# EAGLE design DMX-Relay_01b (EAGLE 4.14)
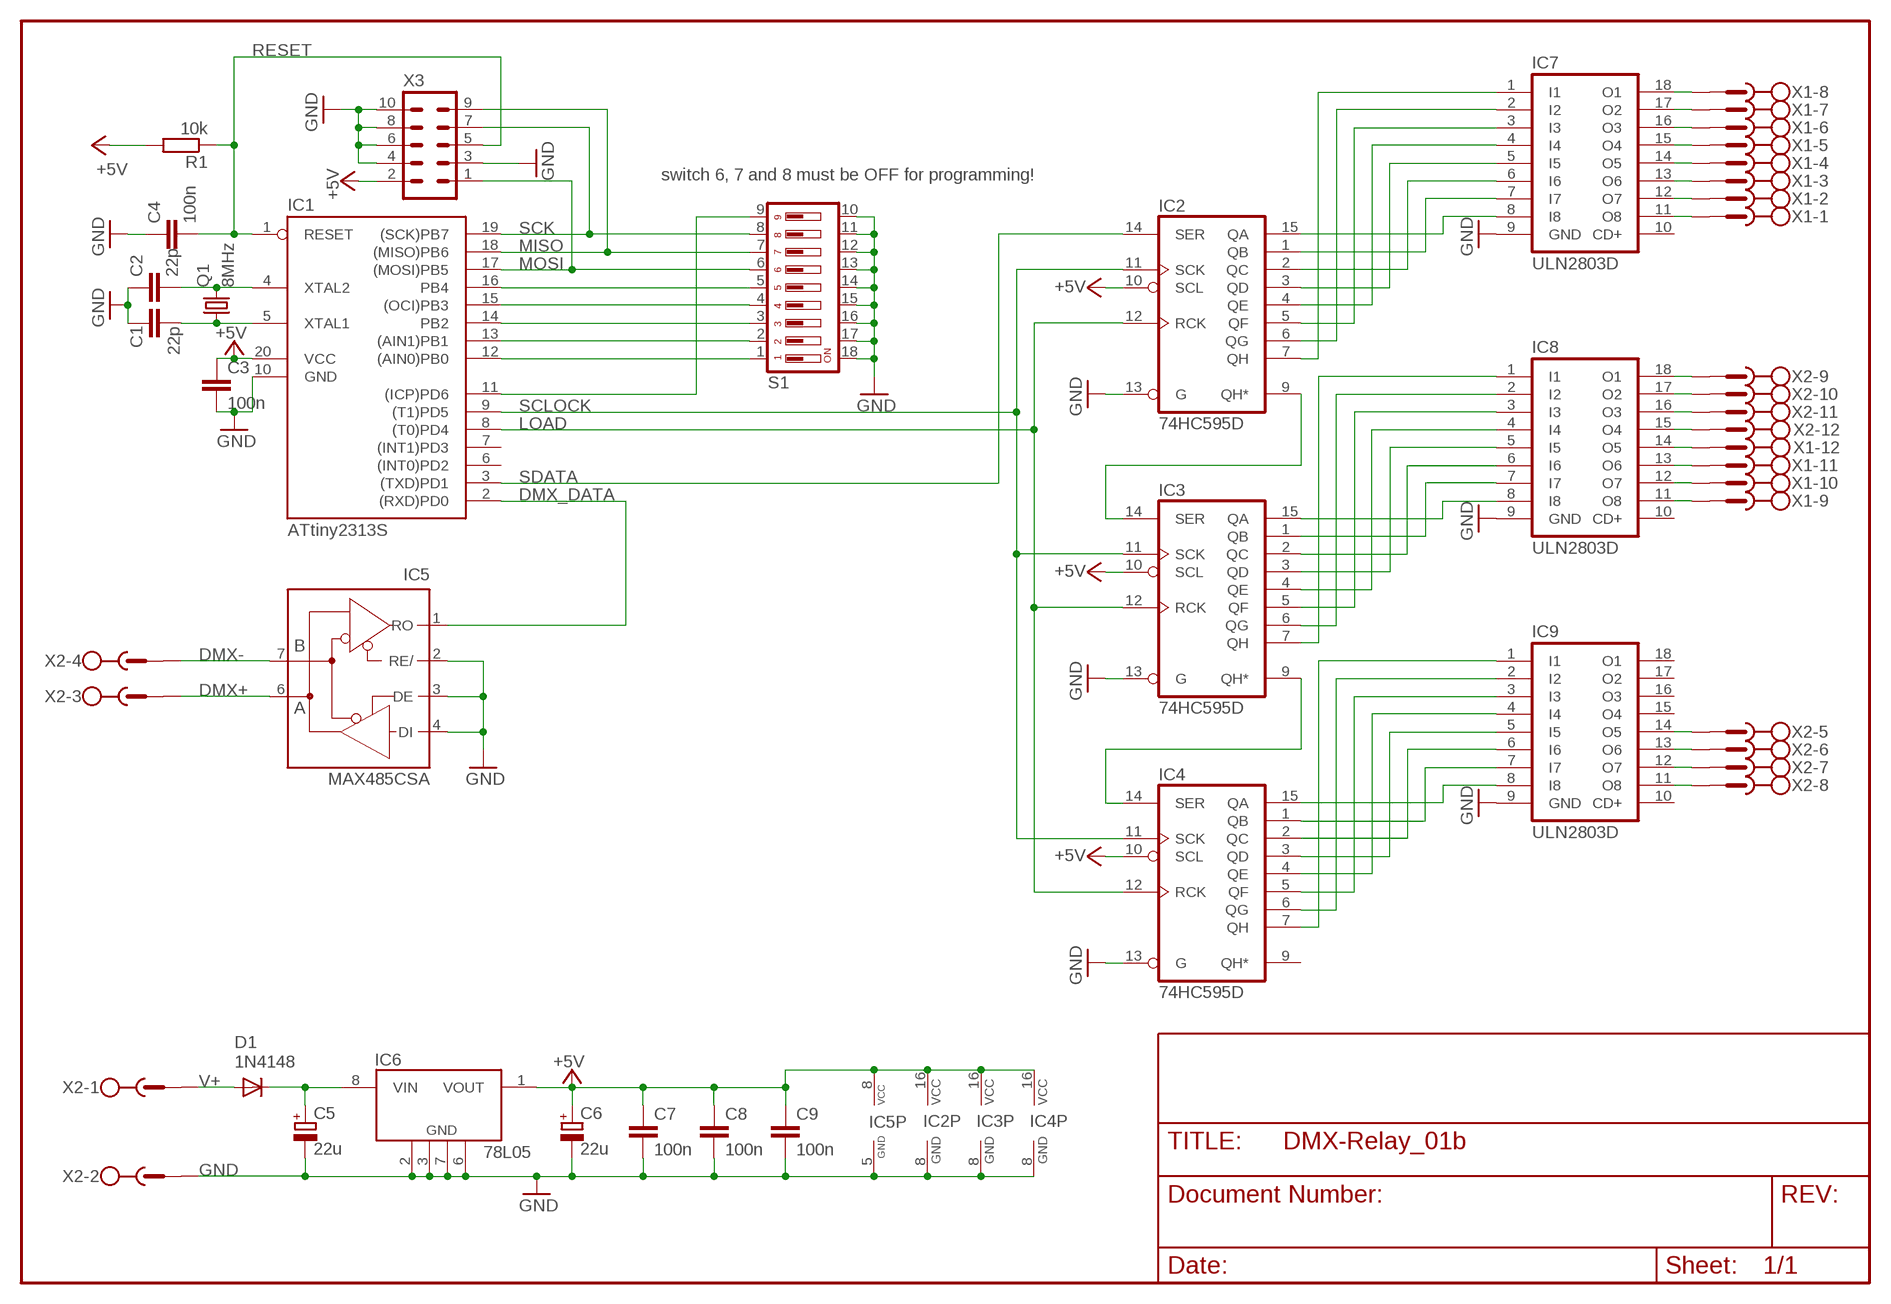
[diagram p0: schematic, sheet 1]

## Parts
C1  22p  C-EUC0805K  [C0805K]
C2  22p  C-EUC0805K  [C0805K]
C3  100n  C-EUC0805K  [C0805K]
C4  100n  C-EUC0805K  [C0805K]
C5  22u  CPOL-EUE2-5  [E2-5]
C6  22u  CPOL-EUE2-5  [E2-5]
C7  100n  C-EUC0805K  [C0805K]
C8  100n  C-EUC0805K  [C0805K]
C9  100n  C-EUC0805K  [C0805K]
D1  1N4148  DIODE-MINIMELF  [MINIMELF]
IC1  ATtiny2313S  AT90S2313S  [SO20W]
IC2  74HC595D  [SO16]
IC3  74HC595D  [SO16]
IC4  74HC595D  [SO16]
IC5  MAX485CSA  MAX481CSA  [SO08]
IC6  78L05  78LXX  [SO8]
IC7  ULN2803D  ULN2803ASOP  [SOP18]
IC8  ULN2803D  ULN2803ASOP  [SOP18]
IC9  ULN2803D  ULN2803ASOP  [SOP18]
Q1  8MHz  CRYTALHC49S  [HC49/S]
R1  10k  R-EU_M0805  [M0805]
S1  DIP09YL  [DIP09YL]
X1  MSTBV12  [MSTBV12]
X2  MSTBV12  [MSTBV12]
X3  ML10  [ML10]

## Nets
+5V: C3.1 C6.+ C7.1 C8.1 C9.1 IC1.20(VCC) IC2.10(SCL) IC2.16(VCC) IC3.10(SCL) IC3.16(VCC) IC4.10(SCL) IC4.16(VCC) IC5.8(VCC) IC6.1(VOUT) R1.2 X3.2
DMX+: IC5.6(A) X2.3
DMX-: IC5.7(B) X2.4
DMX_DATA: IC1.2((RXD)PD0) IC5.1(RO)
GND: C1.1 C2.1 C3.2 C4.1 C5.- C6.- C7.2 C8.2 C9.2 IC1.10(GND) IC2.8(GND) IC2.13(G) IC3.8(GND) IC3.13(G) IC4.8(GND) IC4.13(G) IC5.2(RE/) IC5.3(DE) IC5.4(DI) IC5.5(GND) IC6.2(GND1) IC6.3(GND2) IC6.6(GND4) IC6.7(GND3) IC7.9(GND) IC8.9(GND) IC9.9(GND) S1.10 S1.11 S1.12 S1.13 S1.14 S1.15 S1.16 S1.17 S1.18 X2.2 X3.3 X3.4 X3.6 X3.8 X3.10
LOAD: IC1.8((T0)PD4) IC2.12(RCK) IC3.12(RCK) IC4.12(RCK)
MISO: IC1.18((MISO)PB6) S1.7 X3.9
MOSI: IC1.17((MOSI)PB5) S1.6 X3.1
N$1: IC7.11(O8) X1.1
N$2: C2.2 IC1.4(XTAL2) Q1.2
N$3: C1.2 IC1.5(XTAL1) Q1.1
N$4: IC3.9(QH*) IC4.14(SER)
N$5: IC2.9(QH*) IC3.14(SER)
N$6: C5.+ D1.C IC6.8(VIN)
N$7: IC1.12((AIN0)PB0) S1.1
N$8: IC1.13((AIN1)PB1) S1.2
N$9: IC1.14(PB2) S1.3
N$10: IC7.13(O6) X1.3
N$11: IC7.15(O4) X1.5
N$12: IC1.15((OCI)PB3) S1.4
N$13: IC7.17(O2) X1.7
N$14: IC7.12(O7) X1.2
N$15: IC7.14(O5) X1.4
N$16: IC7.16(O3) X1.6
N$17: IC7.18(O1) X1.8
N$18: IC8.11(O8) X1.9
N$19: IC8.13(O6) X1.11
N$20: IC8.17(O2) X2.10
N$21: IC8.15(O4) X2.12
N$22: IC8.12(O7) X1.10
N$23: IC8.14(O5) X1.12
N$24: IC8.18(O1) X2.9
N$25: IC8.16(O3) X2.11
N$26: IC9.13(O6) X2.6
N$27: IC9.12(O7) X2.7
N$28: IC1.16(PB4) S1.5
N$29: IC3.3(QD) IC8.5(I5)
N$30: IC3.2(QC) IC8.6(I6)
N$31: IC2.7(QH) IC7.1(I1)
N$32: IC2.6(QG) IC7.2(I2)
N$33: IC2.5(QF) IC7.3(I3)
N$34: IC2.4(QE) IC7.4(I4)
N$35: IC2.3(QD) IC7.5(I5)
N$36: IC2.2(QC) IC7.6(I6)
N$37: IC2.1(QB) IC7.7(I7)
N$38: IC2.15(QA) IC7.8(I8)
N$39: IC3.7(QH) IC8.1(I1)
N$40: IC3.6(QG) IC8.2(I2)
N$41: IC3.5(QF) IC8.3(I3)
N$42: IC3.4(QE) IC8.4(I4)
N$43: IC3.1(QB) IC8.7(I7)
N$44: IC3.15(QA) IC8.8(I8)
N$45: IC4.7(QH) IC9.1(I1)
N$46: IC4.6(QG) IC9.2(I2)
N$47: IC4.5(QF) IC9.3(I3)
N$48: IC4.4(QE) IC9.4(I4)
N$49: IC4.3(QD) IC9.5(I5)
N$50: IC4.2(QC) IC9.6(I6)
N$51: IC4.1(QB) IC9.7(I7)
N$52: IC4.15(QA) IC9.8(I8)
N$53: IC9.11(O8) X2.8
N$54: IC9.14(O5) X2.5
N$55: IC1.11((ICP)PD6) S1.9
RESET: C4.2 IC1.1(RESET) R1.1 X3.5
SCK: IC1.19((SCK)PB7) S1.8 X3.7
SCLOCK: IC1.9((T1)PD5) IC2.11(SCK) IC3.11(SCK) IC4.11(SCK)
SDATA: IC1.3((TXD)PD1) IC2.14(SER)
V+: D1.A X2.1
Unconnected: IC1.6((INT0)PD2) IC1.7((INT1)PD3) IC4.9(QH*) IC7.10(CD+) IC8.10(CD+) IC9.10(CD+) IC9.15(O4) IC9.16(O3) IC9.17(O2) IC9.18(O1)

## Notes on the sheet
- switch 6, 7 and 8 must be OFF for programming!

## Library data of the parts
C1-C4 C7-C9 = rcl:C-EU: CAPACITOR, European symbol
C5 C6 = rcl:CPOL-EU: POLARIZED CAPACITOR, European symbol
D1 = diode:DIODE-: DIODE
IC1 = atmel:AT90S2313: MICROCONTROLLER 2 Kbytes FLASH 128 bytes SRAM 128 bytes EEPROM UART
IC2-IC4 = 74xx-eu:74*595: 8-bit SHIFT REGISTER, output latch
IC5 = maxim:MAX481CSA: RS485 TRANSEIVER
IC6 = selfmade:78LXX
IC7-IC9 = selfmade:ULN2803A: DRIVER ARRAY
Q1 = crystal:CRYTAL: CRYSTAL
R1 = rcl:R-EU_: RESISTOR, European symbol
S1 = switch-dil:DIP09YL: DIL/CODE SWITCH
X1 X2 = con-phoenix-500:MSTBV12: PHOENIX
X3 = con-harting-ml:ML10: HARTING

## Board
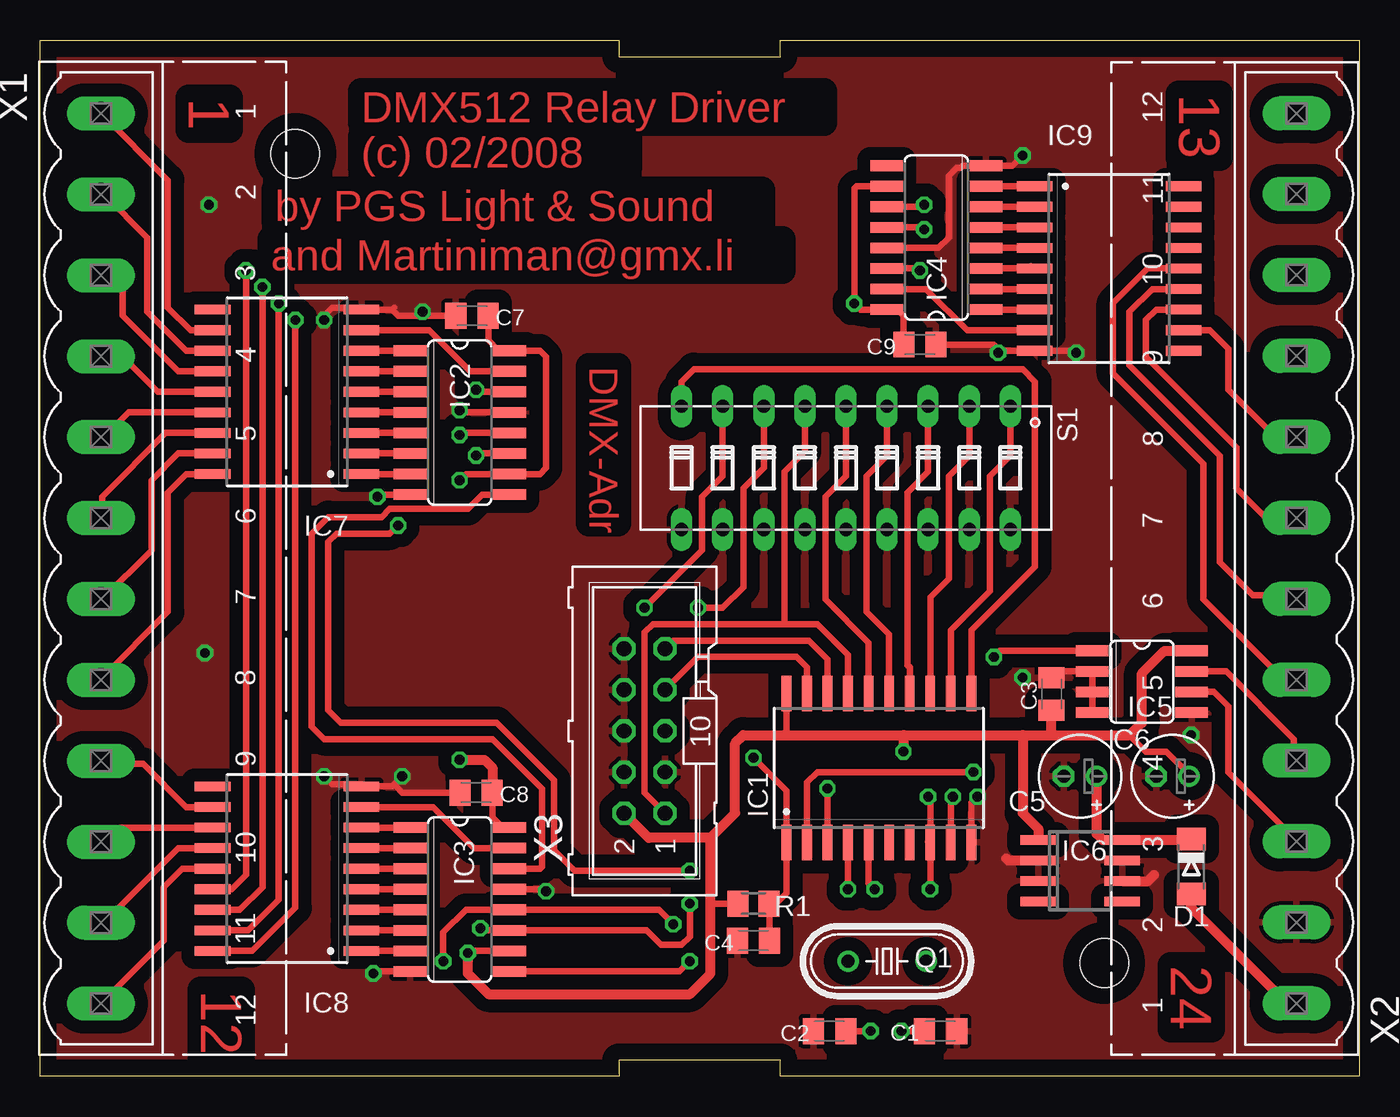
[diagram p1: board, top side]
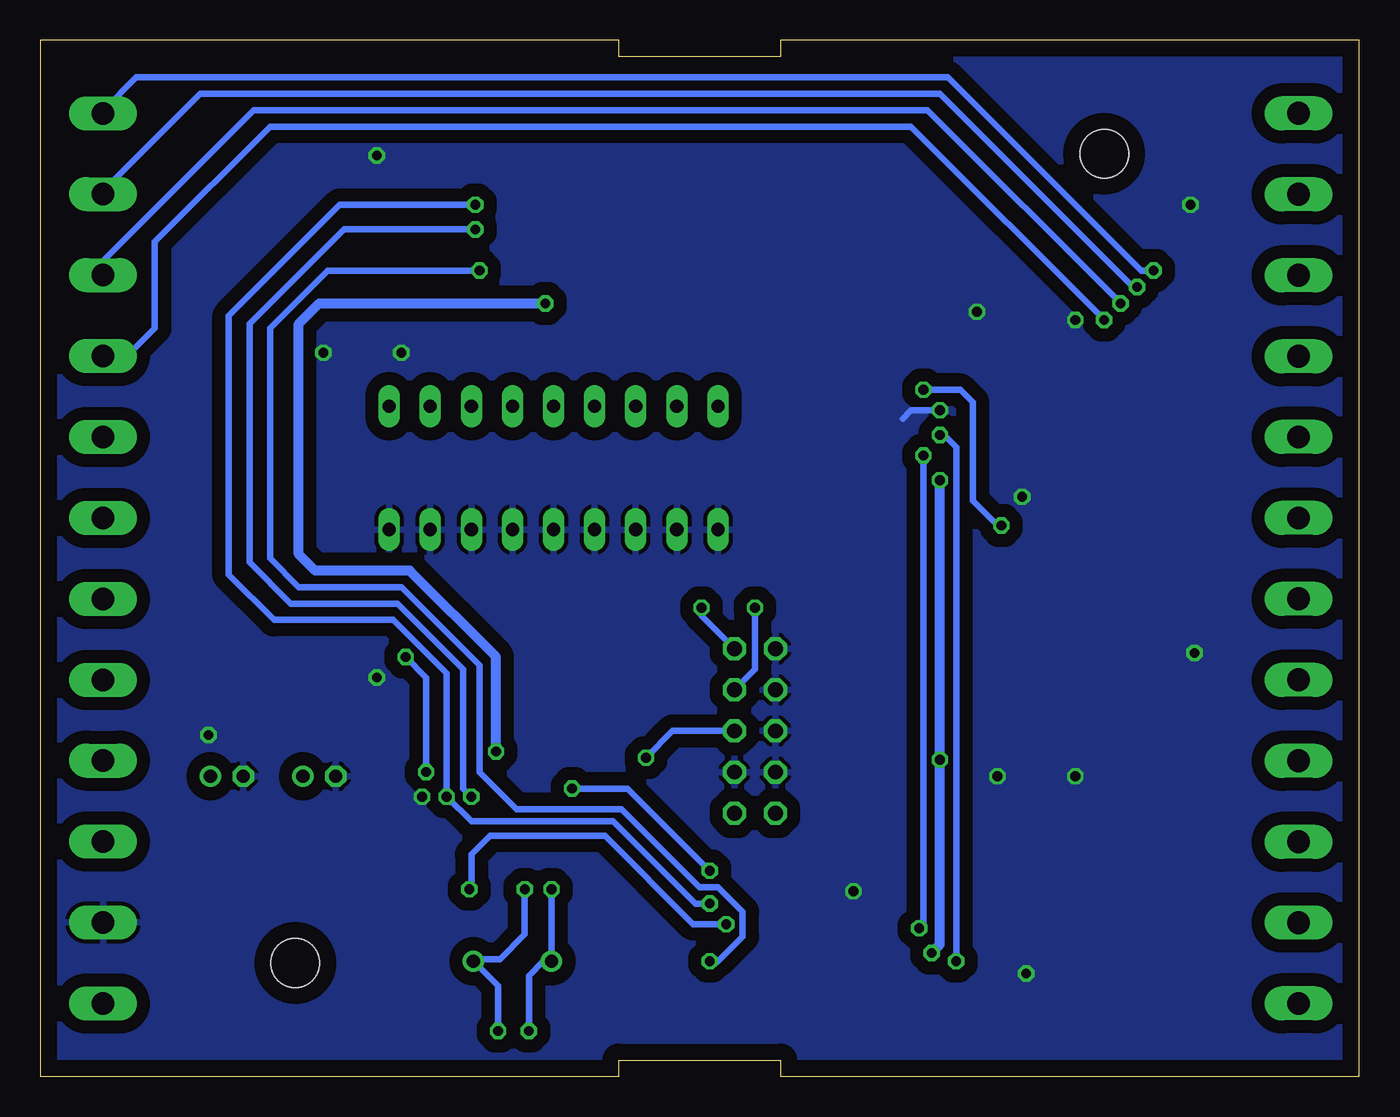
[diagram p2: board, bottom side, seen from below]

Size 81.5 x 64 mm. Coordinates in mm from the lower left corner, seen from the top.
Outline: 0,64 35.75,64 35.75,63 45.75,63 45.75,64 81.5,64 81.5,0 45.75,0 45.75,1 35.75,1 35.75,0 0,0 0,64
Copper layers (1*16): Top 0.035mm / dielectric 1.5mm / Bottom 0.035mm
Design rules "default": minimum track width 10mil, minimum drill 0.6mm, track to track 12mil, track to pad 12mil, pad to pad 12mil, via to via 12mil, smd to smd 8mil, copper to edge 40mil, drill to drill 8mil, minimum pad ring 10mil, minimum via ring 8mil, stop-mask expansion 4mil, vias tented up to drill 0mil, thermal gap 10mil
Holes 3 mm at 15.75,57 65.75,7

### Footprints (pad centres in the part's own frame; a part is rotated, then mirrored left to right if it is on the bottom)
C0805K = smd 1.3 x 1.6: 1 -1,0; 2 1,0
E2-5 = drill 0.813 pad 1.27 round: + -1.016,0 | drill 0.813 pad 1.27 octagon: - 1.016,0
MINIMELF = smd 1.4 x 1.8: A 1.7,0; C -1.7,0
SO20W = smd 0.6 x 2.2: 1 -5.715,-4.6; 2 -4.445,-4.6; 3 -3.175,-4.6; 4 -1.905,-4.6; 5 -0.635,-4.6; 6 0.635,-4.6; 7 1.905,-4.6; 8 3.175,-4.6; 9 4.445,-4.6; 10 5.715,-4.6; 11 5.715,4.6; 12 4.445,4.6; 13 3.175,4.6; 14 1.905,4.6; 15 0.635,4.6; 16 -0.635,4.6; 17 -1.905,4.6; 18 -3.175,4.6; 19 -4.445,4.6; 20 -5.715,4.6
SO16 = smd 0.66 x 2.032: 1 -4.445,-3.073; 2 -3.175,-3.073; 3 -1.905,-3.073; 4 -0.635,-3.073; 5 0.635,-3.073; 6 1.905,-3.073; 7 3.175,-3.073; 8 4.445,-3.073; 9 4.445,3.073; 10 3.175,3.073; 11 1.905,3.073; 12 0.635,3.073; 13 -0.635,3.073; 14 -1.905,3.073; 15 -3.175,3.073; 16 -4.445,3.073
SO08 = smd 0.66 x 2.032: 1 -1.905,-3.073; 2 -0.635,-3.073; 3 0.635,-3.073; 4 1.905,-3.073; 5 1.905,3.073; 6 0.635,3.073; 7 -0.635,3.073; 8 -1.905,3.073
SO8 = smd 0.6 x 2.2: 1 -1.905,-2.6; 2 -0.635,-2.6; 3 0.635,-2.6; 4 1.905,-2.6; 5 1.905,2.6; 6 0.635,2.6; 7 -0.635,2.6; 8 -1.905,2.6
SOP18 = smd 0.6 x 2.2: 1 -5.08,-4.6; 2 -3.81,-4.6; 3 -2.54,-4.6; 4 -1.27,-4.6; 5 0,-4.6; 6 1.27,-4.6; 7 2.54,-4.6; 8 3.81,-4.6; 9 5.08,-4.6; 10 5.08,4.6; 11 3.81,4.6; 12 2.54,4.6; 13 1.27,4.6; 14 0,4.6; 15 -1.27,4.6; 16 -2.54,4.6; 17 -3.81,4.6; 18 -5.08,4.6
HC49/S = drill 0.813 round: 1 -2.413,0; 2 2.413,0
M0805 = smd 1.3 x 1.6: 1 -0.95,0; 2 0.95,0
DIP09YL = drill 0.813 long: 1 -10.16,-3.81; 2 -7.62,-3.81; 3 -5.08,-3.81; 4 -2.54,-3.81; 5 0,-3.81; 6 2.54,-3.81; 7 5.08,-3.81; 8 7.62,-3.81; 9 10.16,-3.81; 10 10.16,3.81; 11 7.62,3.81; 12 5.08,3.81; 13 2.54,3.81; 14 0,3.81; 15 -2.54,3.81; 16 -5.08,3.81; 17 -7.62,3.81; 18 -10.16,3.81
MSTBV12 = drill 1.397 long: 1 -27.5,0; 2 -22.496,0; 3 -17.492,0; 4 -12.489,0; 5 -7.51,0; 6 -2.506,0; 7 2.497,0; 8 7.501,0; 9 12.505,0; 10 17.509,0; 11 22.513,0; 12 27.491,0
ML10 = drill 0.914 octagon: 1 -5.08,-1.27; 2 -5.08,1.27; 3 -2.54,-1.27; 4 -2.54,1.27; 5 0,-1.27; 6 0,1.27; 7 2.54,-1.27; 8 2.54,1.27; 9 5.08,-1.27; 10 5.08,1.27

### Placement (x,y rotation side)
C1  55.63,2.79 180 top
C2  48.77,2.79 0 top
C3  62.49,23.62 90 top
C4  44.07,8.38 0 top
C5  64.27,18.54 180 top
C6  69.98,18.54 180 top
C7  26.67,46.99 180 top
C8  26.93,17.53 180 top
C9  54.36,45.21 0 top
D1  71.12,12.95 270 top
IC1  51.82,19.05 0 top
IC2  25.91,40.39 270 top
IC3  25.91,10.92 270 top
IC4  55.38,51.82 90 top
IC5  68.08,24.38 270 top
IC6  64.27,12.7 270 top
IC7  15.24,42.29 90 top
IC8  15.24,12.83 90 top
IC9  66.04,49.91 270 top
Q1  52.33,7.11 180 top
R1  44.07,10.67 180 top
S1  49.79,37.59 180 top
X1  3.75,32 270 top
X2  77.63,32 90 top
X3  37.34,21.34 90 top

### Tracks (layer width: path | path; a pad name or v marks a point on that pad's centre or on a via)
+5V  (via drill 0.6)
  Top 0.406: IC1.20 46.1,21.21 45.98,21.08 | C7.1 27.67,46.75 27.69,46.74 27.69,45.47 28.32,44.83 IC2.16 30.86,44.83 31.25,44.45 31.25,37.59 30.86,37.21 IC2.10 26.29,37.21 v25.91,36.83 | IC3.16 28.58,15.37 27.94,16 27.94,17.53 C8.1 27.93,17.76 27.94,17.78 | C9.1 53.36,45.45 53.34,45.47 53.34,46.99 52.96,47.37 IC4.16 50.68,47.37 v50.3,47.75 50.3,54.86 50.42,54.99 IC4.10 | IC3.10 26.55,7.75 v26.42,7.62 | 41.41,10.67 R1.2 | C6.+ 71,18.67 69.6,20.07 68.33,20.07 67.31,21.08
  Top 0.61: X3.2 37.6,14.73 41.41,14.73 | 41.41,14.73 42.93,16.26 42.93,20.57 43.44,21.08 45.98,21.08 53.34,21.08 | v25.91,19.56 27.44,19.56 27.94,19.05 27.94,17.78 | 53.34,21.08 v53.34,20.07 | IC6.1 61.67,15.3 60.71,16.26 60.71,21.08 | 53.34,21.08 60.71,21.08 | 60.71,21.08 62.49,21.08 | 62.49,21.08 67.31,21.08 68.08,21.84 68.08,24.89 69.47,26.29 IC5.8 | 62.49,21.08 C3.1 | 41.41,14.73 41.41,10.67 41.41,6.35 40.14,5.08 27.69,5.08 26.42,6.35 v26.42,7.62
  Bottom 0.61: v25.91,36.83 v25.91,19.56 25.91,8.13 v26.42,7.62 | v50.3,47.75 64.27,47.75 65.54,46.48 65.54,32.26 64.52,31.24 58.68,31.24 53.34,25.91 v53.34,20.07
DMX+
  Top 0.406: IC5.6 72.52,23.75 73.41,22.86 73.41,18.8 77.63,14.57 X2.3
DMX-
  Top 0.406: IC5.7 73.28,25.02 77.47,20.83 77.47,19.56 77.52,19.51 X2.4
DMX_DATA  (via drill 0.6)
  Top 0.406: IC5.1 59.31,26.29 v58.93,25.91 | v57.66,18.8 48.01,18.8 47.38,18.16 IC1.2
  Bottom 0.406: v57.66,18.8 57.66,24.64 v58.93,25.91
GND  (via drill 0.6)
  Top 0.305: 61.22,44.83 61.22,44.7 61.34,44.83 IC9.9 | 59.19,44.96 v59.19,44.7
  Top 0.406: 65.03,22.61 65.16,22.48 | 65.03,22.61 65,22.58 IC5.4 | 65.03,22.61 65,22.63 IC5.3 65,23.85 65.03,23.88 65,23.9 IC5.2 63.12,25.02 62.49,24.38 C3.2 | IC1.10 57.53,16.89 v57.92,17.27 | 21.72,47.37 22.1,46.99 C7.2 | 21.98,17.91 22.36,17.53 C8.2 | 59.31,44.83 59.19,44.96 58.93,45.21 C9.2 | v60.71,56.9 60.08,56.26 IC4.8 57.03,56.26 56.9,56.13 56.65,56.13 56.14,55.63 56.14,51.82 55.5,51.18 IC4.13 | IC2.8 20.96,35.94 v20.83,35.81 | IC3.8 20.7,6.48 v20.58,6.35 | IC3.13 31.12,11.56 v31.25,11.43 | IC2.13 26.04,41.02 v25.91,41.15 | IC7.9 21.72,47.37 | 21.72,47.37 21.85,47.5 | IC8.9 21.72,17.91 v22.36,18.54 | 18.04,18.03 19.82,18.03 | 19.82,47.5 18.04,47.5 17.78,47.24 | IC9.9 63.89,44.83 v64.01,44.7 | 59.57,44.83 61.22,44.83 61.34,44.83
  Top 0.61: IC6.2 59.82,13.34 59.69,13.46 | IC6.6 68.46,12.06 68.84,12.45
  Bottom 0.406: v25.91,41.15 27.69,41.15 28.2,40.64
  other vias: 23.63,47.24 10.42,53.85 10.16,26.16 60.71,24.64 71.12,21.08 17.53,18.54 17.53,46.74
  pour Bottom (isolate 0.813): -0.25,64.01 81.03,64.01 81.03,0 -0.25,0
  pour Top (isolate 0.813): -0.25,64.01 81.28,64.01 81.28,0 -0.25,0
LOAD  (via drill 0.6)
  Top 0.406: v54.87,17.27 54.99,17.14 IC1.8 54.99,14.48 | 38.99,9.53 v39.12,9.4 38.23,10.29 IC3.12 26.29,10.29 24.9,8.89 v24.9,7.11 | IC4.12 54.49,52.45 v54.61,52.32 | IC2.12 26.04,39.75 v25.91,39.62 | v54.99,11.56 54.99,14.48 | 54.99,14.48 54.87,14.48
  Bottom 0.406: v39.12,9.4 41.15,9.4 46.61,14.86 53.73,14.86 54.87,13.72 54.87,11.68 v54.99,11.56 | v54.87,17.27 55.38,17.78 55.38,25.15 59.44,29.21 66.04,29.21 68.58,31.75 68.58,46.48 62.74,52.32 v54.61,52.32 | v25.91,39.62 25.66,39.62 24.9,38.86 v24.9,7.11
MISO  (via drill 0.6)
  Top 0.406: IC1.18 48.65,25.78 47.5,26.92 39.12,26.92 X3.9 | v40.64,28.96 42.17,28.96 43.44,30.23 43.44,36.32 44.71,37.59 S1.7
  Bottom 0.406: v40.64,28.96 40.64,28.45 X3.9
MOSI
  Top 0.406: X3.1 37.34,17.53 37.34,27.43 37.85,27.94 45.98,27.94 | IC1.17 49.91,26.04 48.01,27.94 45.98,27.94 | 45.98,27.94 45.98,37.34 47.25,38.61 S1.6
N$1
  Top 0.406: IC7.11 9.28,46.1 7.88,47.5 7.88,55.37 X1.1
N$2  (via drill 0.6)
  Top 0.406: C2.2 v51.31,2.79 | v49.91,11.56 IC1.4
  Bottom 0.406: v51.31,2.79 51.31,6.22 50.42,7.11 Q1.2 v49.91,11.56
N$3  (via drill 0.6)
  Top 0.406: C1.2 v53.22,2.79 | IC1.5 51.19,11.94 v51.57,11.56
  Bottom 0.406: v53.22,2.79 53.22,5.59 Q1.1 54.61,7.24 53.09,7.24 51.57,8.76 v51.57,11.56
N$4  (via drill 0.6)
  Top 0.406: IC4.14 54.23,49.91 v54.36,49.78 | IC3.9 39.5,6.48 v40.14,7.11
  Bottom 0.406: v40.14,7.11 39.63,7.11 38.1,8.64 38.1,10.16 39.63,11.68 40.77,11.68 45.6,16.51 52.07,16.51 54.36,18.8 54.36,25.4 59.19,30.23 65.54,30.23 67.31,32 67.31,46.23 63.76,49.78 v54.36,49.78
N$5
  Top 0.406: IC2.9 27.31,35.94 26.42,35.05 21.59,35.05 21.09,34.54 17.78,34.54 16.77,33.53 16.77,21.59 17.53,20.83 27.94,20.83 30.99,17.78 30.99,12.95 30.86,12.83 IC3.14
N$6
  Top 0.406: 65.66,14.61 IC6.8
  Top 0.61: C5.+ 65.28,14.99 65.66,14.61 | D1.C 71.05,14.65 70.87,14.48 70.74,14.61 IC6.8
N$7
  Top 0.406: IC1.12 56.27,27.56 58.68,29.97 58.68,37.08 59.95,38.35 S1.1
N$8
  Top 0.406: S1.2 57.41,38.35 56.14,37.08 56.14,30.73 54.99,29.59 IC1.13
N$9
  Top 0.406: IC1.14 53.73,25.27 53.6,25.4 53.6,36.07 54.87,37.34 S1.3
N$10
  Top 0.406: IC7.13 8.51,43.56 5.08,46.99 5.08,48.51 4.07,49.53 4.03,49.49 X1.3
N$11
  Top 0.406: X1.5 3.95,39.51 5.46,41.02 IC7.15
N$12
  Top 0.406: IC1.15 52.45,27.3 51.06,28.7 51.06,37.08 52.33,38.35 S1.4
N$13
  Top 0.406: IC7.17 8.51,38.48 6.86,36.83 6.86,32.51 3.81,29.46 3.78,29.5 X1.7
N$14
  Top 0.406: IC7.12 9.02,44.83 6.61,47.24 6.61,51.82 3.93,54.5 X1.2
N$15
  Top 0.406: IC7.14 7.24,42.29 5.08,44.45 4.07,44.45 4.03,44.49 X1.4
N$16
  Top 0.406: IC7.16 7.75,39.75 3.81,35.81 3.81,34.29 3.75,34.35 X1.6
N$17
  Top 0.406: IC7.18 9.02,37.21 7.88,36.07 7.88,28.7 3.75,24.57 X1.8
N$18
  Top 0.406: IC8.11 9.02,16.64 6.35,19.3 4.58,19.3 4.32,19.56 3.81,19.56 X1.9
N$19
  Top 0.406: X1.11 3.75,9.46 3.81,9.4 8.51,14.1 IC8.13
N$20  (via drill 0.6)
  Top 0.406: IC8.17 12.83,9.02 14.74,10.92 v14.74,47.75
  Bottom 0.406: v14.74,47.75 26.67,59.69 68.33,59.69 77.73,50.29 77.73,49.61 X2.10
N$21  (via drill 0.6)
  Top 0.406: IC8.15 11.81,11.56 12.7,12.45 v12.7,49.78
  Bottom 0.406: 77.63,59.47 X2.12 77.63,59.66 75.57,61.72 25.4,61.72 13.47,49.78 v12.7,49.78
N$22
  Top 0.406: X1.10 4.05,14.49 4.07,14.48 4.96,15.37 IC8.12
N$23
  Top 0.406: IC8.14 8.77,12.83 7.62,11.68 7.62,8.38 X1.12
N$24  (via drill 0.6)
  Top 0.406: IC8.18 13.09,7.75 15.75,10.41 v15.75,46.74
  Bottom 0.406: X2.9 77.63,44.48 77.6,44.45 76.84,44.45 76.84,44.58 76.71,44.7 75.95,44.7 74.43,46.23 74.43,51.56 67.31,58.67 27.69,58.67 v15.75,46.74
N$25  (via drill 0.6)
  Top 0.406: IC8.16 12.32,10.29 13.72,11.68 v13.72,48.77
  Bottom 0.406: 77.63,54.58 X2.11 77.63,54.71 71.63,60.71 25.91,60.71 13.97,48.77 v13.72,48.77
N$26
  Top 0.406: IC9.13 68.71,48.64 67.31,47.24 67.31,43.94 72.9,38.35 72.9,31.75 74.93,29.72 77.22,29.72 77.44,29.49 X2.6
N$27
  Top 0.305: X2.7 77.68,34.5 77.73,34.54 77.22,34.54
  Top 0.406: IC9.12 68.97,47.37 68.33,46.74 68.33,44.45 73.92,38.86 73.92,36.32 75.7,34.54 77.22,34.54
N$28
  Top 0.406: IC1.16 51.19,26.8 48.52,29.46 48.52,35.81 49.79,37.08 S1.5
N$29
  Top 0.406: 22.84,12.72 22.86,12.7 | 22.84,12.72 IC3.3 | IC8.5 22.74,12.83 22.84,12.72
N$30
  Top 0.406: 22.84,13.99 22.86,13.97 | 22.84,13.99 IC3.2 | IC8.6 22.74,14.1 22.84,13.99
N$31
  Top 0.406: 22.99,37.21 IC2.7 | IC7.1 22.99,37.21 | 22.99,37.21 23.12,37.08
N$32
  Top 0.406: 22.99,38.48 IC2.6 | IC7.2 22.99,38.48 | 22.99,38.48 23.12,38.35
N$33
  Top 0.406: 22.99,39.75 IC2.5 | IC7.3 22.99,39.75 | 22.99,39.75 23.12,39.62
N$34
  Top 0.406: 22.99,41.02 IC2.4 | IC7.4 22.99,41.02 | 22.99,41.02 23.12,40.89
N$35
  Top 0.406: 22.99,42.29 IC2.3 | IC7.5 22.99,42.29 | 22.99,42.29 23.12,42.16
N$36
  Top 0.406: 22.84,43.46 22.86,43.43 | 22.84,43.46 IC2.2 | IC7.6 22.74,43.56 22.84,43.46
N$37
  Top 0.406: 22.84,44.73 22.86,44.7 | 22.84,44.73 IC2.1 | IC7.7 22.74,44.83 22.84,44.73
N$38
  Top 0.406: IC7.8 24.01,46.1 26.55,43.56 IC2.15
N$39
  Top 0.406: 22.84,7.64 22.86,7.62 | 22.84,7.64 IC3.7 | IC8.1 22.74,7.75 22.84,7.64
N$40
  Top 0.406: 22.84,8.91 22.86,8.89 | 22.84,8.91 IC3.6 | IC8.2 22.74,9.02 22.84,8.91
N$41
  Top 0.406: 22.84,10.19 22.86,10.16 | 22.84,10.19 IC3.5 | IC8.3 22.74,10.29 22.84,10.19
N$42
  Top 0.406: 22.99,11.56 IC3.4 | IC8.4 22.99,11.56 | 22.99,11.56 23.12,11.43
N$43
  Top 0.406: 22.99,15.37 IC3.1 | IC8.7 22.99,15.37 | 22.99,15.37 23.12,15.24
N$44
  Top 0.406: IC8.8 24.26,16.64 26.8,14.1 IC3.15
N$45
  Top 0.406: 58.45,54.89 58.42,54.86 | IC4.7 58.45,54.89 | IC9.1 58.55,54.99 58.45,54.89
N$46
  Top 0.406: IC4.6 58.45,53.82 58.55,53.72 IC9.2
N$47
  Top 0.406: 61.6,52.45 IC9.3 | IC4.5 61.6,52.45 | 61.6,52.45 61.73,52.32
N$48
  Top 0.406: 58.45,51.28 58.42,51.31 | IC4.4 58.45,51.28 | IC9.4 58.55,51.18 58.45,51.28
N$49
  Top 0.406: IC9.5 61.34,49.91 61.22,50.04 61.09,49.91 IC4.3
N$50
  Top 0.406: IC4.2 58.55,48.64 58.68,48.77 58.8,48.64 IC9.6
N$51
  Top 0.406: IC9.7 61.34,47.37 61.22,47.5 61.09,47.37 IC4.1
N$52
  Top 0.406: IC9.8 57.28,46.1 54.74,48.64 IC4.15
N$53
  Top 0.406: IC9.11 72.27,46.1 73.41,44.96 73.41,42.42 76.2,39.62 76.97,39.62 77.22,39.37 77.35,39.5 X2.8 77.63,39.59 77.6,39.62
N$54
  Top 0.406: IC9.14 68.46,49.91 66.3,47.75 66.3,43.43 71.89,37.85 71.89,29.46 76.71,24.64 77.22,24.64 77.47,24.38 77.58,24.49 X2.5
N$55
  Top 0.406: IC1.11 57.53,27.56 61.47,31.5 61.47,42.93 60.71,43.69 40.39,43.69 39.63,42.93 S1.9
RESET  (via drill 0.6)
  Top 0.406: v44.07,19.68 46.1,17.65 IC1.1 46.1,11.3 45.47,10.67 R1.1 45.02,10.61 45.09,10.54 45.07,10.53 C4.2
  Bottom 0.406: v44.07,19.68 42.42,21.34 X3.5
SCK  (via drill 0.6)
  Top 0.406: IC1.19 47.38,25.27 46.74,25.91 40.64,25.91 X3.7 | v37.34,28.96 40.9,32.51 40.9,35.81 42.17,37.08 S1.8
  Bottom 0.406: v37.34,28.96 37.34,25.15 X3.7
SCLOCK  (via drill 0.6)
  Top 0.406: IC1.9 56.27,17.14 v56.39,17.27 | v40.14,10.67 40.14,8.64 39.63,8.13 38.36,8.13 37.47,9.02 IC3.11 27.31,9.02 v27.18,9.14 | IC4.11 54.49,53.72 v54.61,53.85 | IC2.11 27.05,38.48 v26.93,38.35
  Bottom 0.406: v40.14,10.67 41.02,10.67 46.1,15.75 54.87,15.75 v56.39,17.27 56.39,24.89 59.69,28.19 67.06,28.19 69.85,30.99 69.85,46.99 63,53.85 v54.61,53.85 | v27.18,9.14 26.93,9.4 v26.93,38.35
SDATA  (via drill 0.6)
  Top 0.406: v48.65,17.78 IC1.3 | v40.14,12.7 33.02,12.7 31.75,13.97 31.75,18.29 28.2,21.84 18.55,21.84 17.78,22.61 17.78,33.02 18.29,33.53 21.59,33.53 v22.1,34.04 | IC2.14 27.05,42.29 v26.93,42.42
  Bottom 0.406: v40.14,12.7 45.22,17.78 v48.65,17.78 | v22.1,34.04 22.36,34.04 23.88,35.56 23.88,41.66 24.64,42.42 v26.93,42.42
V+
  Top 0.61: D1.A 71.12,10.41 76.97,4.57 77.47,4.57 77.55,4.5 X2.1

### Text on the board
Top: 13 | 1 | DMX512 Relay Driver | (c) 02/2008 | by PGS Light & Sound | and Martiniman@gmx.li | DMX-Adr | 24 | 12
